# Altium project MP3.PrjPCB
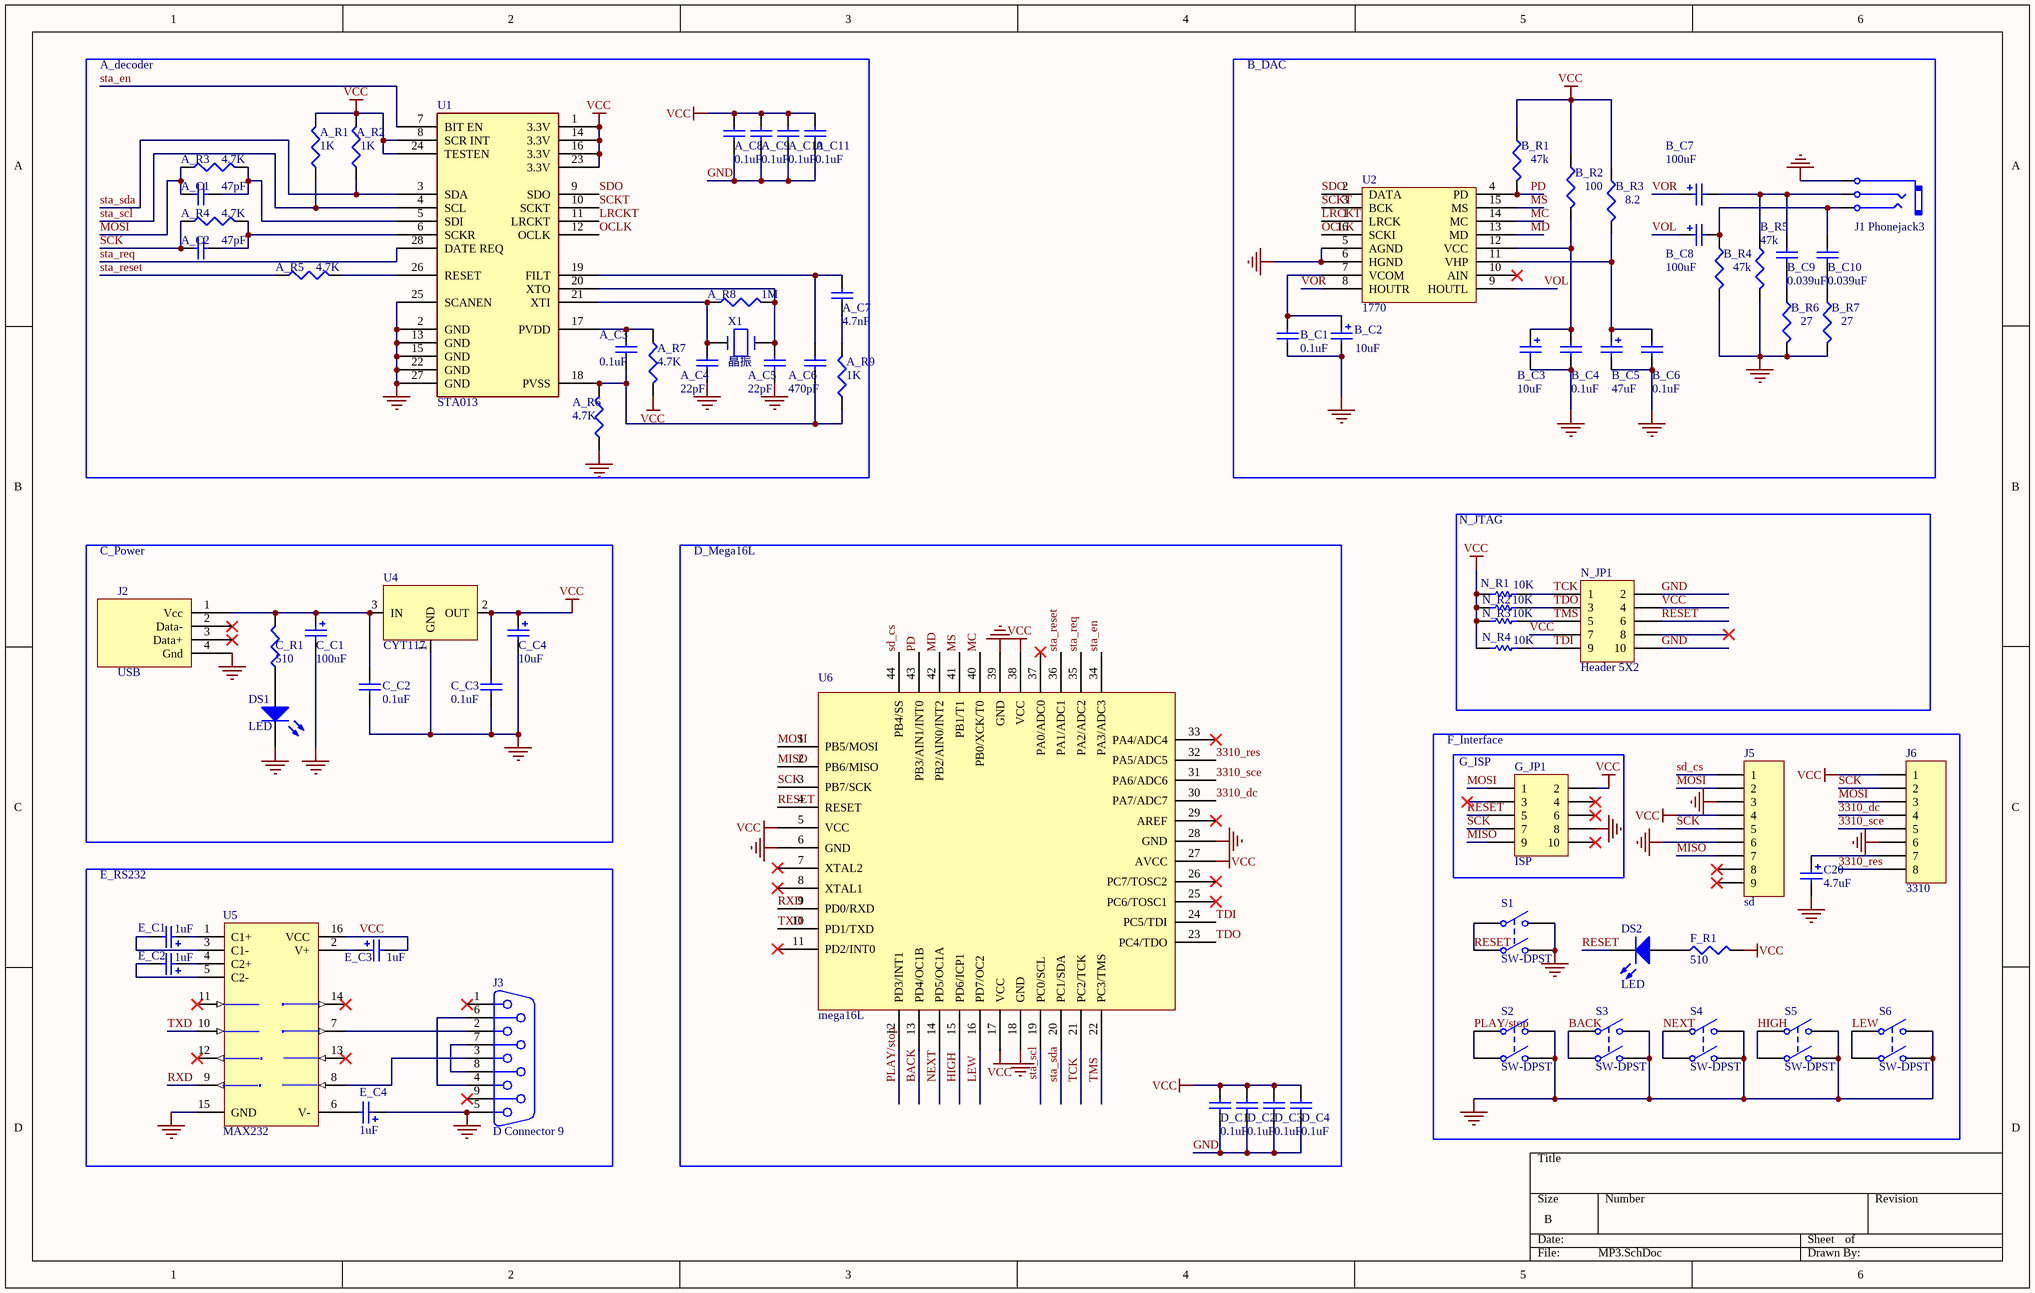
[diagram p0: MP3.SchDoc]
1 sheet, 77 parts. Net scope: global (net labels, ports and power ports of the same name join across sheets).
Board file: MP3.PcbDoc

## Sheet MP3.SchDoc
size B

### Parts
A_C1  value 47pF  [0805]  (hidden comment: Cap Semi)
A_C2  value 47pF  [0805]  (hidden comment: Cap Semi)
A_C3  value 0.1uF  [0805]  (hidden comment: Cap Semi)
A_C4  value 22pF  [0805]  (hidden comment: Cap Semi)
A_C5  value 22pF  [0805]  (hidden comment: Cap Semi)
A_C6  value 470pF  [0805]  (hidden comment: Cap Semi)
A_C7  value 4.7nF  [0805]  (hidden comment: Cap Semi)
A_C8  value 0.1uF  [0805]  (hidden comment: Cap Semi)
A_C9  value 0.1uF  [0805]  (hidden comment: Cap Semi)
A_C10  value 0.1uF  [0805]  (hidden comment: Cap Semi)
A_C11  value 0.1uF  [0805]  (hidden comment: Cap Semi)
A_R1  value 1K  [0805]  (hidden comment: Res3)
A_R2  value 1K  [0805]  (hidden comment: Res3)
A_R3  value 4.7K  [0805]  (hidden comment: Res3)
A_R4  value 4.7K  [0805]  (hidden comment: Res3)
A_R5  value 4.7K  [0805]  (hidden comment: Res3)
A_R6  value 4.7K  [0805]  (hidden comment: Res3)
A_R7  value 4.7K  [0805]  (hidden comment: Res3)
A_R8  value 1M  [0805]  (hidden comment: Res3)
A_R9  value 1K  [0805]  (hidden comment: Res3)
B_C1  value 0.1uF  [0805]  (hidden comment: Cap Semi)
B_C2  value 10uF  [1210]  (hidden comment: Cap Pol3)
B_C3  value 10uF  [1210]  (hidden comment: Cap Pol3)
B_C4  value 0.1uF  [0805]  (hidden comment: Cap Semi)
B_C5  value 47uF  [C_model]  (hidden comment: Cap Pol3)
B_C6  value 0.1uF  [0805]  (hidden comment: Cap Semi)
B_C7  value 100uF  [D_model]  (hidden comment: Cap Pol3)
B_C8  value 100uF  [D_model]  (hidden comment: Cap Pol3)
B_C9  value 0.039uF  [0805]  (hidden comment: Cap Semi)
B_C10  value 0.039uF  [0805]  (hidden comment: Cap Semi)
B_R1  value 47k  [0805]  (hidden comment: Res3)
B_R2  value 100  [0805]  (hidden comment: Res3)
B_R3  value 8.2  [0805]  (hidden comment: Res3)
B_R4  value 47k  [0805]  (hidden comment: Res3)
B_R5  value 47k  [0805]  (hidden comment: Res3)
B_R6  value 27  [0805]  (hidden comment: Res3)
B_R7  value 27  [0805]  (hidden comment: Res3)
C20  value 4.7uF  [1206]  (hidden comment: Cap Pol3)
C_C1  value 100uF  [D_model]  (hidden comment: Cap Pol3)
C_C2  value 0.1uF  [0805]  (hidden comment: Cap Semi)
C_C3  value 0.1uF  [0805]  (hidden comment: Cap Semi)
C_C4  value 10uF  [1210]  (hidden comment: Cap Pol3)
C_R1  value 510  [0805]  (hidden comment: Res3)
D_C1  value 0.1uF  [0805]  (hidden comment: Cap Semi)
D_C2  value 0.1uF  [0805]  (hidden comment: Cap Semi)
D_C3  value 0.1uF  [0805]  (hidden comment: Cap Semi)
D_C4  value 0.1uF  [0805]  (hidden comment: Cap Semi)
DS1  LED  [0805]
DS2  LED  [0805]
E_C1  value 1uF  [1206]
E_C2  value 1uF  [1206]
E_C3  value 1uF  [1206]
E_C4  value 1uF  [1206]
F_R1  value 510  [0805]  (hidden comment: Res3)
G_JP1  ISP  [ISP_2]
J1  Phonejack3  [耳机插座3]
J2  USB  [USB]
J3  D Connector 9  [232_9PIN]
J5  sd  [SD Card]
J6  3310  [nokia3310]
N_JP1  Header 5X2  [ISP_2]
N_R1  value 10K  [0805]
N_R2  value 10K  [0805]
N_R3  value 10K  [0805]
N_R4  value 10K  [0805]
S1  SW-DPST  [key_top]
S2  SW-DPST  [key_top]
S3  SW-DPST  [key_top]
S4  SW-DPST  [key_top]
S5  SW-DPST  [key_top]
S6  SW-DPST  [key_top]
U1  STA013  [STA013]
U2  1770  [pcm1770]
U4  CYT117  [CYT117]
U5  MAX232  [NSO16]
U6  mega16L  [贴片Mega16L]
X1  晶振  [jinzhen]

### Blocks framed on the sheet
A_decoder: A_C1-A_C11 A_R1-A_R9 U1 X1
B_DAC: B_C1-B_C10 B_R1-B_R7 J1 U2
C_Power: C_C1-C_C4 C_R1 DS1 J2 U4
D_Mega16L: D_C1-D_C4 U6
N_JTAG: N_JP1 N_R1-N_R4
F_Interface: C20 DS2 F_R1 J5 J6 S1-S6
G_ISP: G_JP1
E_RS232: E_C1-E_C4 J3 U5

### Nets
GND: A_C4.1 A_C5.1 A_C8.2 A_C9.2 A_C10.2 A_C11.2 A_R6.1 B_C1.1 B_C2.2 B_C3.2 B_C4.1 B_C5.2 B_C6.1 B_R4.2 B_R5.2 B_R6.2 B_R7.2 C20.2 C_C1.2 C_C2.1 C_C3.1 C_C4.2 D_C1.2 D_C2.2 D_C3.2 D_C4.2 DS1.2(K) E_C4.1 G_JP1.8 J1.3(C) J2.4(Gnd) J3.5 J5.3 J5.6 J6.6 N_JP1.2 N_JP1.10 S1.2(NO1) S1.4(NO2) S2.2(NO1) S2.4(NO2) S3.2(NO1) S3.4(NO2) S4.2(NO1) S4.4(NO2) S5.2(NO1) S5.4(NO2) S6.2(NO1) S6.4(NO2) U1.2(GND) U1.13(GND) U1.15(GND) U1.22(GND) U1.25(SCANEN) U1.27(GND) U2.5(AGND) U2.6(HGND) U4.1(GND) U5.15(GND) U6.6(GND) U6.18(GND) U6.28(GND) U6.39(GND)
VCC: A_C8.1 A_C9.1 A_C10.1 A_C11.1 A_R1.2 A_R2.2 A_R7.2 B_R1.1 B_R2.1 B_R3.1 C_C3.2 C_C4.1 D_C1.1 D_C2.1 D_C3.1 D_C4.1 E_C3.2 F_R1.2 G_JP1.2 J5.4 J6.1 N_JP1.4 N_JP1.7 N_R1.2 N_R2.2 N_R3.2 N_R4.2 U1.1(3.3V) U1.8(SCR_INT) U1.14(3.3V) U1.16(3.3V) U1.23(3.3V) U1.24(TESTEN) U4.2(OUT) U5.16(VCC) U6.5(VCC) U6.17(VCC) U6.27(AVCC) U6.38(VCC)
3310_dc: J6.4 U6.30(PA7/ADC7)
3310_res: J6.8 U6.32(PA5/ADC5)
3310_sce: J6.5 U6.31(PA6/ADC6)
BACK: S3.1(COMMON1) S3.3(COMMON2) U6.13(PD4/OC1B)
HIGH: S5.1(COMMON1) S5.3(COMMON2) U6.15(PD6/ICP1)
LEW: S6.1(COMMON1) S6.3(COMMON2) U6.16(PD7/OC2)
LRCKT: U1.11(LRCKT) U2.1(LRCK)
MC: U2.14(MC) U6.40(PB0/XCK/T0)
MD: U2.13(MD) U6.42(PB2/AIN0/INT2)
MISO: G_JP1.9 J5.7 U6.2(PB6/MISO)
MOSI: A_C1.1 A_R3.1 G_JP1.1 J5.2 J6.3 U6.1(PB5/MOSI)
MS: U2.15(MS) U6.41(PB1/T1)
NEXT: S4.1(COMMON1) S4.3(COMMON2) U6.14(PD5/OC1A)
OCLK: U1.12(OCLK) U2.16(SCKI)
PD: B_R1.2 U2.4(PD) U6.43(PB3/AIN1/INT0)
PLAY/stop: S2.1(COMMON1) S2.3(COMMON2) U6.12(PD3/INT1)
RESET: DS2.2(K) G_JP1.5 N_JP1.6 S1.1(COMMON1) S1.3(COMMON2) U6.4(RESET)
RXD: U5.9(R2OUT) U6.9(PD0/RXD)
SCK: A_C2.1 A_R4.1 G_JP1.7 J5.5 J6.2 U6.3(PB7/SCK)
SCKT: U1.10(SCKT) U2.3(BCK)
sd_cs: J5.1 U6.44(PB4/SS)
SDO: U1.9(SDO) U2.2(DATA)
sta_en: U1.7(BIT_EN) U6.34(PA3/ADC3)
sta_req: U1.28(DATE_REQ) U6.35(PA2/ADC2)
sta_reset: A_R5.1 U6.36(PA1/ADC1)
sta_scl: A_R1.1 U1.4(SCL) U6.19(PC0/SCL)
sta_sda: A_R2.1 U1.3(SDA) U6.20(PC1/SDA)
TCK: N_JP1.1 N_R1.1 U6.21(PC2/TCK)
TDI: N_JP1.9 N_R4.1 U6.24(PC5/TDI)
TDO: N_JP1.3 N_R2.1 U6.23(PC4/TDO)
TMS: N_JP1.5 N_R3.1 U6.22(PC3/TMS)
TXD: U5.10(T2IN) U6.10(PD1/TXD)
VOL: B_C8.1 U2.9(HOUTL)
VOR: B_C7.1 U2.8(HOUTR)
NetA_C1_2: A_C1.2 A_R3.2 U1.5(SDI)
NetA_C2_2: A_C2.2 A_R4.2 U1.6(SCKR)
NetA_C3_1: A_C3.1 A_C6.1 A_R6.2 A_R9.1 U1.18(PVSS)
NetA_C3_2: A_C3.2 A_R7.1 U1.17(PVDD)
NetA_C4_2: A_C4.2 A_R8.1 U1.21(XTI) X1.2
NetA_C5_2: A_C5.2 A_R8.2 U1.20(XTO) X1.1
NetA_C6_2: A_C6.2 A_C7.2 U1.19(FILT)
NetA_C7_1: A_C7.1 A_R9.2
NetA_R5_2: A_R5.2 U1.26(RESET)
NetB_C1_2: B_C1.2 B_C2.1 U2.7(VCOM)
NetB_C3_1: B_C3.1 B_C4.2 B_R2.2 U2.12(VCC)
NetB_C5_1: B_C5.1 B_C6.2 B_R3.2 U2.11(VHP)
NetB_C7_2: B_C7.2 B_C9.2 B_R5.1 J1.2(B)
NetB_C8_2: B_C8.2 B_C10.2 B_R4.1 J1.1(A)
NetB_C9_1: B_C9.1 B_R6.1
NetB_C10_1: B_C10.1 B_R7.1
NetC20_1: C20.1 J6.7
NetC_C1_1: C_C1.1 C_C2.2 C_R1.2 J2.1(Vcc) U4.3(IN)
NetC_R1_1: C_R1.1 DS1.1(A)
NetDS2_1: DS2.1(A) F_R1.1
NetE_C1_1: E_C1.1 U5.1(C1+)
NetE_C1_2: E_C1.2 U5.3(C1-)
NetE_C2_1: E_C2.1 U5.4(C2+)
NetE_C2_2: E_C2.2 U5.5(C2-)
NetE_C3_1: E_C3.1 U5.2(V+)
NetE_C4_2: E_C4.2 U5.6(V-)
NetJ3_2: J3.2 U5.7(T2OUT)
NetJ3_3: J3.3 U5.8(R2IN)
NetJ3_4: J3.4 J3.6
NetJ3_7: J3.7 J3.8

Not connected (* = marked no-connect by the designer): G_JP1 3* 4* 6* 10*; J2 2(Data-)* 3(Data+)*; J3 1* 9*; J5 8* 9*; N_JP1 8*; U2 10(AIN)*; U5 11(T1IN)* 12(R1OUT)* 13(R1IN)* 14(T1OUT)*; U6 7(XTAL2)* 8(XTAL1)* 11(PD2/INT0)* 25(PC6/TOSC1)* 26(PC7/TOSC2)* 29(AREF)* 33(PA4/ADC4)* 37(PA0/ADC0)*

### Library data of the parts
A_C1-A_C11 B_C1 B_C4 B_C6 B_C9 B_C10 C_C2 C_C3 D_C1-D_C4 = Cap Semi: Capacitor (Semiconductor SIM Model)
A_R1-A_R9 B_R1-B_R7 C_R1 F_R1 = Res3: Resistor
B_C2 B_C3 B_C5 B_C7 B_C8 C20 C_C1 C_C4 = Cap Pol3: Polarized Capacitor (Surface Mount)
DS1 DS2 = LED3: Typical BLUE SiC LED; Revision 1: Jul-2002: Re-released for DXP Platform.; Revision 2: 17-Dec-2003: PCB Footprint replaced.
E_C1-E_C4 = Cap Pol1: Polarized Capacitor (Radial); Manufacturer: Generic Components; Class: Passive
G_JP1 N_JP1 = Header 5X2: Header, 5-Pin, Dual row
J1 = Phonejack3: 3-Conductor Jack
J3 = D Connector 9: Receptacle Assembly, 9 Position, Right Angle; Manufacturer: Generic Components; Positions: 9
J5 = Header 9: Header, 9-Pin
J6 = Header 8: Header, 8-Pin
N_R1-N_R4 = Res Semi: Semiconductor Resistor; Manufacturer: Generic Components; Class: Passive
S1-S6 = SW-DPST: Double-Pole, Single-Throw Switch
U5 = MAX3232CPE: 3.0V TO 5.5V, Low-Power, up to 1Mbps, True RS-232 Transceiver Using Four 0.1µF External Capacitor; Package Information: Latest Revision: Aug-2000; Code - JEDEC: MS-001-BB
U6 = minimega16l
